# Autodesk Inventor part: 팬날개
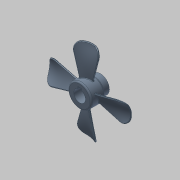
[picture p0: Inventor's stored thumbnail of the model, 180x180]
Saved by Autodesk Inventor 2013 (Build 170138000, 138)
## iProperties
Company: 한국ATC센터
Created: 2016-06
Part Number: 팬날개
Document SubType Name: Modeling
Designer: mdu
Density: 1.493 g/cm^3
Material: ABS 플라스틱
Mass: 1497.56 g
Surface Area: 466.268 cm^2
Volume: 190.529 cm^3
Author: mdu
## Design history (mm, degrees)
sketch "스케치1"
  geometry: L1 (-15, 0)-(15, 0); L2 (-15, 0)-(-15, 17); L3 (-15, 17)-(5, 17); L4 (5, 17)-(5, 13); L5 (5, 13)-(15, 13); L6 (15, 13)-(15, 0); 2 further points
  constraints: 12 end point, 3 parallel, 2 perpendicular, 1 coincident, 1 horizontal, 1 midpoint
  dimensions: "d0" = 30 distance of L1.start L1.end; "d8" = 34 diameter of L3 L1; "d10" = 26 diameter of L5 L1; "d32" = 20 distance of L2.end L3.end
revolve "회전1" sketch "스케치1" stored, may be unused: angle "d11" = 90 deg
node "작업 평면2"
sketch "스케치7"
  geometry: L1 (-15, 17)-(5, 17) reference; L2 (-15, -17)-(5, -17) reference; L3 (-5, 17)-(-5, -17); A1 r 35 centre (-36.399, -13.457) between (-2, -7) and (-8, 7); 1 further point
  constraints: 2 end point, 2 midpoint, 2 point on circle, 1 centre point
  dimensions: "d36" = 35 radius of A1; "d37" = 10 distance from line of A1.start L2; "d38" = 10 distance from line of A1.end L1; "d45" = 3 distance from line of A1.end L3; "d46" = 3 distance from line of A1.start L3
sketch "3D 스케치1"
  geometry: L1 through (0, 0) direction (1, 0) reference; L2 through (0, 0) direction (1, 0) reference; 13 other entities
  constraints: 2 collinear
  node "투영 원본 위치 스케치7"
sketch "스케치8"
  geometry: L1 (-15, 17)-(5, 17) reference; L2 (-15, -17)-(5, -17) reference; L3 (-5, 17)-(-5, -17); A1 r 30 centre (-28.74, -3.591) between (-3, -19) and (-9, 19); 1 further point
  constraints: 2 end point, 2 midpoint, 2 point on circle, 1 centre point
  dimensions: "d43" = 30 radius of A1; "d47" = 4 distance from line of A1.end L3; "d48" = 2 distance from line of A1.start L3; "d58" = 2 distance from line of A1.end L1; "d59" = 2 distance from line of A1.start L2
sketch "3D 스케치2"
sketch "3D 스케치3"
feature "경계 패치1" sketch "3D 스케치2", "3D 스케치3" dims "d50" = 0
feature "연장1" dims "d55" = 2
feature "두껍게 하기1" dims "d51" = 2, "d52" = 2
sketch "스케치9"
  geometry: C1 r 59 at (0, 0); 1 further point
  constraints: 1 centre point, 1 coincident
  dimensions: "d60" = 118 diameter of C1
extrude "돌출2" sketch "스케치9" distance "d62" = 200; taper "d63" = 0 deg
fillet "모깎기6" dims "d64" = 10
fillet "모깎기7" dims "d66" = 0.8
fillet "모깎기8" dims "d67" = 0.8
sketch "스케치2"
  geometry: L1 (-2.5, 8.124)-(-2.5, 10.8); L2 (-2.5, 10.8)-(2.5, 10.8); L3 (2.5, 10.8)-(2.5, 8.124); A1 r 8.5 centre (0, 0) between (-2.5, 8.124) and (2.5, 8.124); 1 further point
  constraints: 6 end point, 2 parallel, 2 point on circle, 1 centre point, 1 coincident, 1 horizontal, 1 vertical
  dimensions: "d12" = 17 diameter of A1; "d13" = 5 distance of L1.end L2.end; "d14" = 19.3 dimension on A1 L2 (computed from d12)
extrude "돌출1" cut sketch "스케치2" stored distance "d15" = 10; taper "d16" = 0 deg
chamfer "모따기1" distance "d17" = 1; stored, may be unused: second distance "d18" = 2, angle "d19" = 45 deg
node "작업 평면1"
sketch "스케치3"
  geometry: L1 (5, -13)-(5, 13) reference; 3 further points
  constraints: 1 horizontal alignment, 1 midpoint
  dimensions: "d20" = 5 distance from line of L1 point (0, 0)
hole "구멍1" sketch "스케치3" at (0, 0) diameter "d21" = 3.242; stored, may be unused: countersink angle "d25" = 90 deg, drill point angle "d27" = 118 deg; dims "d22" = 6, "d23" = 4, "d24" = 2, "d26" = 8
fillet "모깎기9" dims "d77" = 2
fillet "모깎기10" dims "d78" = 2
fillet "모깎기11" dims "d79" = 2
node "솔리드1"
pattern_circular "원형 패턴1" dims "d69" = 360 deg
pattern_circular "원형 패턴2" dims angle "d72" = 360 deg
pattern_circular "원형 패턴3" dims angle "d75" = 360 deg
node "투영 원본 위치 스케치8"
node "곡면1"
node "곡면2"
node "곡면3"
node "곡면4"
feature "경계 패치2"
feature "경계 패치3"
feature "경계 패치4"
